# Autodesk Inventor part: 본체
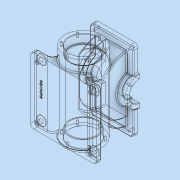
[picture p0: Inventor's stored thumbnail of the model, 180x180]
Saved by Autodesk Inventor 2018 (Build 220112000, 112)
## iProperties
Created: 2023-07
Part Number: 본체
Material: 일반
Document SubType Name: Modeling
Designer: home
Density: 1 g/cm^3
Appearance: 기본값
Author: home
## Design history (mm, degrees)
sketch "스케치1"
  geometry: L1 (90, 100)-(-90, 100); L2 (-100, 90)-(-100, -90); L3 (-90, -100)-(90, -100); L4 (100, -90)-(100, 90); L5 (100, 100)-(-100, -100); L6 (-100, 100)-(100, -100); A1 r 10 centre (90, -90) between (90, -100) and (100, -90); A2 r 10 centre (90, 90) between (100, 90) and (90, 100); A3 r 10 centre (-90, 90) between (-90, 100) and (-100, 90); A4 r 10 centre (-90, -90) between (-100, -90) and (-90, -100); 1 further point
  constraints: 12 end point, 8 point on circle, 8 point on line, 8 tangent, 4 centre point, 3 equal radius, 2 midpoint, 2 parallel, 1 horizontal, 1 perpendicular
  dimensions: "d0" = 200 distance of L6.end L5.end; "d1" = 200 distance of L5.end L6.start; "d2" = 10 radius of A1
extrude "돌출1" new body sketch "스케치1" distance "d3" = 15; taper "d4" = 0 deg
sketch "스케치2"
  geometry: C1 r 55 at (0, 60); 1 further point
  constraints: 1 centre point, 1 vertical alignment
  dimensions: "d6" = 110 diameter of C1; "d7" = 60 distance of C1.centre point (0, 0)
extrude "돌출2" join sketch "스케치2" distance "d8" = 135; taper "d10" = 0 deg; dims "d9" = 107, "d11" = 0
node "작업 평면1"
sketch "스케치3"
  geometry: L1 (55, 120)-(-55, 120); L2 (-65, 110)-(-65, -110); L3 (-55, -120)-(55, -120); L4 (65, -110)-(65, 110); L5 (65, 120)-(-65, -120); L6 (-65, 120)-(65, -120); A1 r 10 centre (-55, -110) between (-65, -110) and (-55, -120); A2 r 10 centre (55, -110) between (55, -120) and (65, -110); A3 r 10 centre (55, 110) between (65, 110) and (55, 120); A4 r 10 centre (-55, 110) between (-55, 120) and (-65, 110); 1 further point
  constraints: 12 end point, 8 point on circle, 8 point on line, 8 tangent, 4 centre point, 3 equal radius, 2 midpoint, 2 parallel, 1 horizontal, 1 perpendicular
  dimensions: "d13" = 130 distance of L6.end L5.end; "d14" = 240 distance of L5.end L6.start; "d15" = 10 radius of A1 (derived)
extrude "돌출3" join sketch "스케치3" distance "d16" = 15; taper "d17" = 0 deg
sketch "스케치4"
  geometry: L1 (160, 110)-(160, -110) reference; L2 (160, -100)-(160, 100); A1 r 100 centre (160, 0) between (160, 100) and (160, -100); 1 further point
  constraints: 2 end point, 2 point on circle, 2 point on line, 1 centre point, 1 midpoint
  dimensions: "d18" = 200 diameter of A1
extrude "돌출4" join sketch "스케치4" stored distance "d19" = 90; taper "d20" = 0 deg
sketch "스케치5"
  geometry: L1 (0, 0)-(160, 0); L2 (160, 110)-(160, -110) reference; L3 (160, -45)-(160, 45); A1 r 45 centre (160, 0) between (160, 45) and (160, -45)
  constraints: 4 end point, 2 point on circle, 2 point on line, 1 centre point, 1 coincident, 1 horizontal
  dimensions: "d21" = 160 distance of L1.start L1.end; "d22" = 90 diameter of A1
extrude "돌출5" join sketch "스케치5" stored distance "d23" = 140; taper "d24" = 0 deg
sketch "스케치6"
  geometry: C1 r 42.5 at (0, 0); 1 further point
  constraints: 1 centre point, 1 vertical alignment
  dimensions: "d25" = 85 diameter of C1; "d26" = 60 distance of C1.centre point (0, -60)
extrude "돌출6" cut sketch "스케치6" distance "d27" = 25; taper "d28" = 0 deg
sketch "스케치7"
  geometry: L1 (0, 0)-(105.716, 0); L2 (0, 0)-(92.031, 0); L3 (-48.5, 0)-(48.5, 0); 7 further points
  constraints: 6 end point, 3 horizontal, 3 symmetric about line, 1 point on line
  dimensions: "d32" = 60 distance from line of point (0, -60) L1; "d33" = 24.25 distance from line of point (42.002, 24.25) L1; "d34" = 48.5 distance from line of point (0, 48.5) L1; "d35" = 24.25 distance from line of point (-42.002, 24.25) L1; "d36" = 121.55595 distance of point (0, -60) L1.end; "d37" = 109.86261 distance of point (0, -60) L2.end; "d38" = 77.15083 distance of point (0, -60) L3.end; "d39" = 60 distance of point (0, -60) L1.start; "d40" = 77.15083 distance of point (0, -60) L3.start; "d41" = 94.13952 distance of point (42.002, 24.25) point (0, -60); "d42" = 108.5 distance of point (0, 48.5) point (0, -60); "d43" = 94.13952 distance of point (-42.002, 24.25) point (0, -60)
hole "구멍1" sketch "스케치7" at (0, 48.5), (-42.002, 24.25), (42.002, 24.25), (-42.002, -24.25), (0, -48.5), (42.002, -24.25) diameter "d44" = 4.134; stored, may be unused: countersink angle "d48" = 90 deg, drill point angle "d50" = 118 deg; dims "d45" = 10, "d46" = 4, "d47" = 2, "d49" = 12
sketch "스케치8"
  geometry: C1 r 42.5 at (0, 0); 1 further point
  constraints: 1 centre point, 1 vertical alignment
  dimensions: "d51" = 85 diameter of C1; "d67" = 60 distance of point (0, -60) C1.centre
extrude "돌출7" cut sketch "스케치8" distance "d52" = 25; taper "d53" = 0 deg
sketch "스케치9"
  geometry: L1 (0, 0)-(76.957, 0); L2 (0, 0)-(88.148, 0); C1 r 2.067 at (42.002, 24.25) reference; C2 r 2.067 at (0, 48.5) reference; C3 r 2.067 at (-42.002, 24.25) reference; 7 further points
  constraints: 4 end point, 3 coincident, 2 horizontal
  dimensions: "d68" = 24.25 distance from line of C1.centre L1; "d69" = 24.25 distance from line of point (42.002, -24.25) L1; "d70" = 48.5 distance from line of point (0, -48.5) L1; "d71" = 24.25 distance from line of point (-42.002, -24.25) L1; "d72" = 52.12986 distance of C1.centre L2.end; "d73" = 42.54312 distance of C1.centre L1.end; "d74" = 48.5 distance of C1.centre point (42.002, -24.25); "d75" = 48.5 distance of C1.centre L1.start; "d76" = 84.00446 distance of C1.centre point (0, -48.5); "d77" = 97 distance of C1.centre point (-42.002, -24.25)
hole "구멍2" sketch "스케치9" at (42.002, 24.25), (0, 48.5), (-42.002, 24.25), (-42.002, -24.25), (0, -48.5), (42.002, -24.25) diameter "d57" = 4.134; stored, may be unused: countersink angle "d61" = 90 deg, drill point angle "d63" = 118 deg; dims "d58" = 10, "d59" = 4, "d60" = 2, "d62" = 12
sketch "스케치10"
  geometry: L1 (-90, -60)-(90, -60) reference; C1 r 38.5 at (0, 0); 2 further points
  constraints: 1 centre point, 1 midpoint, 1 vertical alignment
  dimensions: "d64" = 77 diameter of C1; "d78" = 60 distance of point (0, -60) C1.centre
extrude "돌출8" cut sketch "스케치10" distance "d65" = 256.25; taper "d66" = 0 deg
sketch "스케치11"
  geometry: L1 (45, 160)-(-45, 160) reference; L2 (0, 160)-(0, 0); C1 r 31 at (0, 159.997)
  constraints: 2 end point, 1 centre point, 1 midpoint, 1 vertical, 1 vertical alignment
  dimensions: "d79" = 62 diameter of C1; "d80" = 159.99726 distance of C1.centre L2.end; "d81" = 0.00274 distance from line of C1.centre L1
extrude "돌출9" cut sketch "스케치11" distance "d82" = 23; taper "d83" = 0 deg
sketch "스케치12"
  geometry: L1 (45, 160)-(-45, 160) reference; C1 r 31 at (0, 160); 1 further point
  constraints: 1 centre point, 1 midpoint
  dimensions: "d84" = 62 diameter of C1
extrude "돌출10" cut sketch "스케치12" distance "d85" = 23; taper "d86" = 0 deg
sketch "스케치13"
  geometry: L1 (-31, 160)-(31, 160) reference; C1 r 27.5 at (0, 160); 1 further point
  constraints: 1 centre point, 1 midpoint
  dimensions: "d87" = 55 diameter of C1
extrude "돌출11" cut sketch "스케치13" distance "d88" = 101.5; taper "d89" = 0 deg
sketch "스케치14"
  geometry: L1 (0, 0)-(160, 0); C1 r 87 at (160, 0)
  constraints: 2 end point, 1 centre point, 1 coincident, 1 horizontal
  dimensions: "d90" = 160 distance of L1.start L1.end; "d91" = 87 radius of C1
extrude "돌출12" cut sketch "스케치14" stored distance "d92" = 64; taper "d93" = 0 deg
sketch "스케치15"
  geometry: L1 (0, 160)-(55.748, 160); L2 (0, 160)-(108.428, 160); A1 r 27.5 centre (0, 160) between (-27.5, 160) and (27.5, 160) reference; A2 r 37 centre (0, 160) between (-26.163, 133.837) and (26.163, 133.837); 1 further point
  constraints: 4 end point, 2 horizontal, 2 point on circle, 1 centre point, 1 coincident
  dimensions: "d94" = 74 diameter of A2; "d97" = 26.16295 distance from line of A2.end L1; "d98" = 26.16295 distance from line of A2.start L1; "d99" = 80.9282 distance of A1.end L2.end; "d100" = 28.24757 distance of A1.end L1.end
hole "구멍3" sketch "스케치15" at (-26.163, 133.837), (26.163, 133.837) diameter "d101" = 4.134; stored, may be unused: countersink angle "d105" = 90 deg, drill point angle "d107" = 118 deg; dims "d102" = 10, "d103" = 4, "d104" = 2, "d106" = 12
node "작업 평면2"
sketch "스케치16"
  geometry: L1 (-55, 120)-(55, 120) reference; L2 (100, -90)-(100, 90) reference; L3 (-100, 90)-(-100, -90) reference; 4 further points
  dimensions: "d113" = 48 distance from line of point (52, 107) L2; "d114" = 48 distance from line of point (52, -107) L2; "d115" = 227 distance from line of point (52, -107) L1; "d116" = 152 distance from line of point (-52, -107) L2; "d117" = 227 distance from line of point (-52, -107) L1; "d118" = 13 distance from line of point (52, 107) L1; "d119" = 152 distance from line of point (-52, 107) L2; "d120" = 13 distance from line of point (-52, 107) L1
hole "구멍4" sketch "스케치16" at (52, 107), (-52, 107), (52, -107), (-52, -107) diameter "d121" = 4.917; stored, may be unused: countersink angle "d125" = 90 deg, drill point angle "d127" = 0 deg; dims "d122" = 12, "d123" = 4, "d124" = 2, "d126" = 15
sketch "스케치17"
  geometry: L1 (-31.623, 15)-(-90, 15) reference; L2 (-90, 15)-(-100, 15) reference; L3 (-63.246, 15)-(-31.623, 15); L4 (31.623, 15)-(63.246, 15); A1 r 15 centre (-63.246, 30) between (-63.246, 15) and (-49.693, 36.429); A2 r 15 centre (63.246, 30) between (49.693, 36.429) and (63.246, 15); A3 r 55 centre (0, 60) between (-49.693, 36.429) and (-31.623, 15); A4 r 55 centre (0, 60) between (31.623, 15) and (49.693, 36.429); 2 further points
  constraints: 8 point on circle, 5 tangent, 4 centre point, 4 end point, 2 horizontal, 1 coincident, 3 other
  dimensions: "d129" = 30 diameter of A1; "d130" = 30 diameter of A2; "d131" = 55 radius of A3
extrude "돌출13" join sketch "스케치17" stored distance "d132" = 200; taper "d133" = 0 deg
sketch "스케치18"
  geometry: L1 (-100, 90)-(-100, -90) reference; L2 (0, 0)-(0, 80); L3 (0, 80)-(-80, 80); L4 (55, 107)-(-55, 107) reference; L5 (-55, -135)-(55, -135) reference; 4 further points
  constraints: 4 end point, 1 coincident, 1 perpendicular, 1 vertical
  dimensions: "d135" = 80 distance of L2.start L2.end; "d136" = 80 distance of L2.end L3.end; "d137" = 27 distance from line of point (80, 80) L4; "d138" = 180 distance from line of point (80, 80) L1; "d139" = 187 distance from line of point (80, -80) L4; "d140" = 180 distance from line of point (80, -80) L1; "d141" = 187 distance from line of point (-80, -80) L4; "d142" = 20 distance from line of point (-80, -80) L1
hole "구멍5" sketch "스케치18" at (-80, 80), (80, 80), (-80, -80), (80, -80) diameter "d143" = 11; stored, may be unused: countersink angle "d147" = 90 deg, drill point angle "d149" = 0 deg; dims "d144" = 13, "d145" = 28, "d146" = 2, "d148" = 15
sketch "스케치19"
  geometry: L1 (-81.179, 24.887)-(-81.179, -24.887); L2 (-81.179, -24.887)-(-85, -24.887); L3 (-85, -24.887)-(-85, 24.887); L4 (-85, 24.887)-(-81.179, 24.887); L5 (-81.179, -24.887)-(-81.179, 24.887); L6 (-81.179, 24.887)-(-85, 24.887); L7 (-85, 24.887)-(-85, -24.887); L8 (-85, -24.887)-(-81.179, -24.887); L9 (-83.09, -24.887)-(-83.09, 24.887); L10 (-81.179, 0)-(-85, 0); L11 (-100, 90)-(-100, -90) reference; 1 further point
  constraints: 12 end point, 4 midpoint, 3 parallel, 1 perpendicular, 2 other
  dimensions: "d150" = 15 distance from line of L11 L10.end; "d151" = 0 vertical distance of L10.end point (0, 0); "d152" = 90 deg angle of L4 L11; "d153" = 18.82098 distance between parallel lines of L5 L11; "d154" = 49.77477 distance between parallel lines of L4 L2
feature "엠보싱1" sketch "스케치19" dims "d0" = 200, "d1" = 200, "d2" = 10, "d155" = 0.5, "d156" = 0
fillet "모깎기1" dims "d157" = 1, "d158" = 3, "d159" = 1.1
chamfer "모따기1" distance "d160" = 1; stored, may be unused: second distance "d161" = 2, angle "d162" = 45 deg
chamfer "모따기2" distance "d163" = 1; stored, may be unused: second distance "d164" = 2, angle "d165" = 45 deg
chamfer "모따기3" distance "d166" = 1; stored, may be unused: second distance "d167" = 2, angle "d168" = 45 deg
chamfer "모따기4" distance "d169" = 1; stored, may be unused: second distance "d170" = 2, angle "d171" = 45 deg
node "솔리드1"
mirror "미러1"
other parameters: "d108" = 0
